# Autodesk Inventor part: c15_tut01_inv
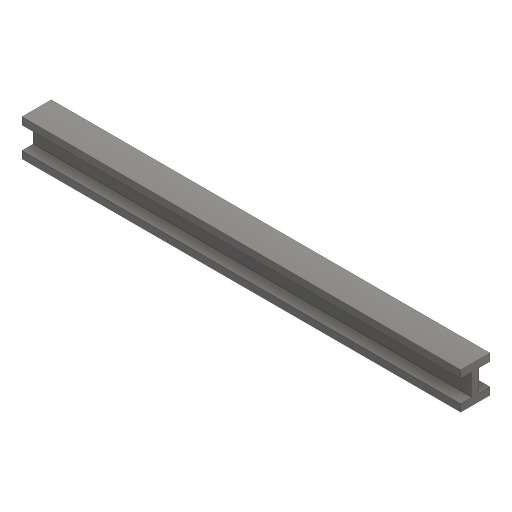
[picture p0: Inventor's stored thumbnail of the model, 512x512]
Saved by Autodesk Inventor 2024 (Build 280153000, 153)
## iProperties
Created: 2017-05
Part Number: c15_tut01_inv
Material: Steel, Alloy
Document SubType Name: Modeling
Designer: CADCIM 00
Mass: 637.725 g
Surface Area: 365.5 cm^2
Volume: 82.5 cm^3
Density: 7.73 g/cm^3
Appearance: Semi-Polished
Author: CADCIM 00
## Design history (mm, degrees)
sketch "Sketch1"
  geometry: L1 (-10, 25)-(10, 25); L2 (10, 25)-(10, 20); L3 (10, 20)-(2.5, 20); L4 (2.5, 20)-(2.5, 5); L5 (2.5, 5)-(10, 5); L6 (10, 5)-(10, 0); L7 (10, 0)-(-10, 0); L8 (-10, 0)-(-10, 5); L9 (-10, 5)-(-2.5, 5); L10 (-2.5, 5)-(-2.5, 20); L11 (-2.5, 20)-(-10, 20); L12 (-10, 25)-(-10, 20); 2 further points
  constraints: 24 end point, 8 perpendicular, 7 point on line, 2 collinear, 1 coincident, 1 horizontal, 1 midpoint
  dimensions: "d0" = 20 distance of L1.start L1.end; "d1" = 5 distance between parallel lines of L3 L1; "d2" = 15 distance between parallel lines of L5 L3; "d3" = 5 distance between parallel lines of L4 L10
extrude "Extrusion1" new body sketch "Sketch1" distance "d4" = 300; taper "d5" = 0 deg
body "Solid1"
other parameters: "sa_0" = 0, "sa_1" = 0, "sa_2" = -1000000
